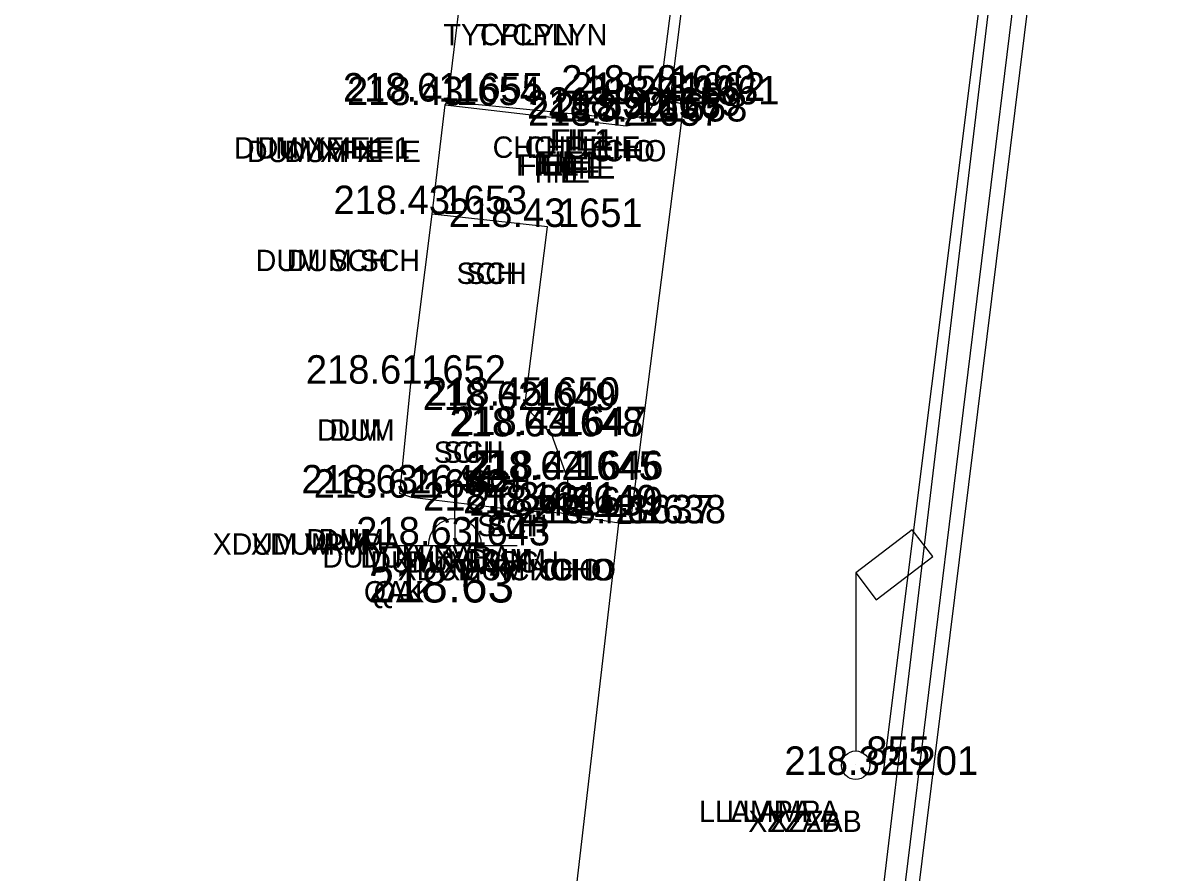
# Model space of a CAD drawing. Extents: x -471047 to -470889, y -1102859 to -1102000.
# Drawn here: x -470984.24 to -470967.99, y -1102446.24 to -1102434.32 of the extents above; entities that cross this region are included whole.
import ezdxf

# ---------------------------------------------------------------- set-up
doc = ezdxf.new("R2010")
doc.units = 0
for name, color, linetype in [('Vrstva 1', 7, 'Continuous'), ('Vrstva 10', 7, 'Continuous'), ('Vrstva 13', 7, 'Continuous'), ('Vrstva 17', 7, 'Continuous'), ('Vrstva 2', 7, 'Continuous'), ('Vrstva 22', 7, 'Continuous'), ('Vrstva 23', 7, 'Continuous'), ('Vrstva 28', 7, 'Continuous'), ('Vrstva 34', 7, 'Continuous'), ('Vrstva 35', 7, 'Continuous'), ('Vrstva 36', 7, 'Continuous'), ('Vrstva 38', 7, 'Continuous'), ('Vrstva 5', 7, 'Continuous'), ('Vrstva 7', 7, 'Continuous'), ('Vrstva 8', 7, 'Continuous')]:
    doc.layers.add(name, color=color, linetype=linetype)

msp = doc.modelspace()

# ---------------------------------------------------------------- linework, layer by layer
at = {"layer": 'Vrstva 1'}
for points in [[(-471040.344, -1102858.385), (-471031.676, -1102846.187), (-471026.357, -1102838.629), (-471023.212, -1102833.975), (-471019.21, -1102827.465), (-471016.861, -1102823.272), (-471013.099, -1102815.912), (-471010.824, -1102810.955), (-471007.329, -1102802.292), (-471005.34, -1102796.515), (-471002.842, -1102787.838), (-471001.3, -1102780.997), (-471000.19, -1102774.713), (-470999.247, -1102768.204), (-470998.794, -1102764.784), (-470997.199, -1102751.812), (-470994.899, -1102732.807), (-470992.551, -1102713.262), (-470990.326, -1102694.887), (-470988.122, -1102676.57), (-470985.812, -1102657.305), (-470983.537, -1102638.407), (-470981.386, -1102620.622), (-470979.843, -1102608.014), (-470976.377, -1102579.253), (-470972.945, -1102550.69), (-470970.475, -1102530.206), (-470967.905, -1102508.801), (-470965.053, -1102485.131), (-470962.734, -1102465.9), (-470960.173, -1102444.812), (-470957.795, -1102425.103), (-470954.965, -1102401.839), (-470953.834, -1102392.574), (-470952.33, -1102379.985), (-470950.744, -1102366.853), (-470948.978, -1102352.106), (-470947.037, -1102335.844), (-470944.949, -1102318.462), (-470944.013, -1102310.745), (-470942.39, -1102297.267), (-470939.519, -1102273.45), (-470937.593, -1102257.43), (-470936.064, -1102244.81), (-470934.114, -1102228.634), (-470931.621, -1102207.856), (-470929.536, -1102190.857), (-470926.572, -1102166.31), (-470924.91, -1102152.663), (-470923.413, -1102140.333), (-470921.923, -1102127.669), (-470921.155, -1102120.084), (-470920.446, -1102109.574), (-470919.912, -1102099.137), (-470919.63, -1102088.981), (-470919.523, -1102081.193), (-470919.563, -1102070.395), (-470919.714, -1102064.236), (-470920.134, -1102054.704), (-470920.462, -1102047.615), (-470920.599, -1102044.52), (-470920.743, -1102041.873), (-470921.125, -1102034.455), (-470921.774, -1102030.337), (-470922.418, -1102027.787), (-470923.734, -1102023.93), (-470924.872, -1102021.434), (-470926.752, -1102018.182), (-470927.953, -1102016.45), (-470929.616, -1102014.424), (-470932.252, -1102011.756), (-470935.111, -1102009.425), (-470938.391, -1102007.371), (-470942.651, -1102005.401)], [(-471041.328, -1102857.18), (-471032.144, -1102844.242), (-471027.583, -1102837.763), (-471024.388, -1102833.028), (-471020.451, -1102826.6), (-471018.089, -1102822.378), (-471014.542, -1102815.445), (-471012.233, -1102810.418), (-471009.247, -1102803.108), (-471006.795, -1102796.098), (-471004.315, -1102787.532), (-471002.782, -1102780.723), (-471001.674, -1102774.458), (-471000.75, -1102768.095), (-471000.28, -1102764.601), (-470998.692, -1102751.741), (-470996.378, -1102732.635), (-470994.028, -1102713.058), (-470991.808, -1102694.749), (-470989.616, -1102676.447), (-470987.284, -1102657.013), (-470985.031, -1102638.272), (-470982.87, -1102620.431), (-470981.334, -1102607.933), (-470977.881, -1102579.263), (-470974.429, -1102550.492), (-470971.964, -1102530.054), (-470969.391, -1102508.607), (-470966.54, -1102484.984), (-470964.231, -1102465.853), (-470961.679, -1102444.752), (-470959.304, -1102425.078), (-470956.455, -1102401.634), (-470955.339, -1102392.489), (-470953.812, -1102379.71), (-470952.249, -1102366.808), (-470950.479, -1102352.023), (-470948.536, -1102335.868), (-470946.426, -1102318.233), (-470945.493, -1102310.531), (-470943.864, -1102297.013), (-470940.984, -1102273.071), (-470939.078, -1102257.195), (-470937.559, -1102244.684), (-470935.592, -1102228.353), (-470933.101, -1102207.653), (-470931.011, -1102190.57), (-470928.046, -1102166.021), (-470926.409, -1102152.578), (-470924.898, -1102140.121), (-470923.427, -1102127.544), (-470922.647, -1102119.826), (-470921.919, -1102109.229), (-470921.42, -1102099.134), (-470921.127, -1102089.016), (-470921.023, -1102081.453), (-470921.061, -1102070.468), (-470921.209, -1102064.314), (-470921.666, -1102053.966), (-470922.156, -1102043.345), (-470922.299, -1102039.934), (-470922.637, -1102034.36), (-470923.091, -1102031.241), (-470923.847, -1102028.247), (-470925.083, -1102024.594), (-470926.222, -1102022.086), (-470928.04, -1102018.943), (-470929.138, -1102017.357), (-470930.929, -1102015.175), (-470933.062, -1102013.049), (-470936.379, -1102010.368), (-470939.169, -1102008.662), (-470942.899, -1102006.906), (-470945.661, -1102005.908)], [(-471043.557, -1102855.955), (-471035.129, -1102844.026), (-471029.872, -1102836.499), (-471026.577, -1102831.578), (-471022.675, -1102825.415), (-471020.123, -1102821.053), (-471016.667, -1102814.59), (-471014.208, -1102809.45), (-471011.177, -1102802.451), (-471008.55, -1102795.333), (-471006.082, -1102787.209), (-471004.464, -1102780.376), (-471003.265, -1102774.167), (-471002.327, -1102767.948), (-471001.636, -1102762.527), (-471000.297, -1102751.605), (-470997.959, -1102732.524), (-470995.602, -1102712.802), (-470993.412, -1102694.623), (-470991.21, -1102676.17), (-470988.891, -1102656.857), (-470986.625, -1102638.083), (-470984.455, -1102620.195), (-470982.936, -1102607.733), (-470979.497, -1102579.223), (-470976.023, -1102550.279), (-470973.554, -1102529.822), (-470970.991, -1102508.497), (-470968.146, -1102484.787), (-470965.835, -1102465.72), (-470963.284, -1102444.529), (-470960.91, -1102424.942), (-470958.043, -1102401.343), (-470956.946, -1102392.356), (-470955.396, -1102379.408), (-470953.851, -1102366.636), (-470952.049, -1102351.733), (-470950.124, -1102335.611), (-470948.034, -1102318.083), (-470947.094, -1102310.328), (-470945.421, -1102296.51), (-470942.58, -1102272.848), (-470940.675, -1102256.948), (-470939.176, -1102244.526), (-470937.187, -1102228.174), (-470934.708, -1102207.467), (-470932.621, -1102190.433), (-470929.634, -1102165.778), (-470928.004, -1102152.415), (-470926.45, -1102139.595), (-470925.003, -1102127.418), (-470924.249, -1102119.695), (-470923.515, -1102109.093), (-470923.018, -1102099.069), (-470922.711, -1102088.911), (-470922.643, -1102081.356), (-470922.797, -1102070.414), (-470923.018, -1102064.454), (-470923.52, -1102053.203), (-470923.823, -1102047.529), (-470924.123, -1102041.506), (-470924.462, -1102037.486), (-470924.934, -1102031.904), (-470925.664, -1102028.672), (-470926.771, -1102025.506), (-470927.959, -1102022.914), (-470929.674, -1102020.028), (-470930.76, -1102018.498), (-470932.447, -1102016.478), (-470935.215, -1102013.816), (-470937.644, -1102011.98), (-470940.381, -1102010.371), (-470943.968, -1102008.669), (-470947.145, -1102007.524), (-470950.874, -1102006.74)], [(-471044.756, -1102855.056), (-471036.376, -1102843.177), (-471031.167, -1102835.741), (-471027.859, -1102830.8), (-471023.934, -1102824.593), (-471021.43, -1102820.312), (-471018.011, -1102813.91), (-471015.536, -1102808.75), (-471012.578, -1102801.897), (-471009.95, -1102794.77), (-471007.561, -1102786.914), (-471005.936, -1102780.074), (-471004.727, -1102773.818), (-471003.828, -1102767.827), (-471003.121, -1102762.345), (-471001.787, -1102751.467), (-470999.446, -1102732.348), (-470997.073, -1102712.539), (-470994.902, -1102694.521), (-470992.696, -1102676.023), (-470990.376, -1102656.68), (-470988.131, -1102638.071), (-470985.947, -1102620.018), (-470984.417, -1102607.512), (-470980.993, -1102579.08), (-470977.514, -1102550.137), (-470975.048, -1102529.649), (-470972.488, -1102508.37), (-470969.618, -1102484.508), (-470967.34, -1102465.669), (-470964.767, -1102444.39), (-470962.402, -1102424.781), (-470959.534, -1102401.193), (-470958.432, -1102392.151), (-470956.883, -1102379.208), (-470955.335, -1102366.424), (-470953.535, -1102351.506), (-470951.606, -1102335.399), (-470949.519, -1102317.94), (-470948.575, -1102310.159), (-470946.889, -1102296.144), (-470944.056, -1102272.618), (-470942.139, -1102256.659), (-470940.657, -1102244.341), (-470938.638, -1102227.749), (-470936.19, -1102207.298), (-470934.102, -1102190.255), (-470931.124, -1102165.639), (-470929.492, -1102152.254), (-470927.915, -1102139.252), (-470926.46, -1102127.103), (-470925.74, -1102119.604), (-470925.012, -1102108.913), (-470924.523, -1102099.054), (-470924.217, -1102088.866), (-470924.148, -1102081.334), (-470924.301, -1102070.391), (-470924.518, -1102064.43), (-470924.97, -1102054.435), (-470925.588, -1102041.569), (-470925.963, -1102035.313), (-470926.405, -1102032.225), (-470927.078, -1102029.198), (-470928.123, -1102026.148), (-470929.318, -1102023.558), (-470930.84, -1102020.97), (-470931.868, -1102019.515), (-470933.443, -1102017.605), (-470936.26, -1102014.885), (-470938.429, -1102013.255), (-470941.213, -1102011.639), (-470944.847, -1102009.927), (-470947.723, -1102008.912), (-470951.444, -1102008.161), (-470954.511, -1102007.931), (-470957.895, -1102008.041)]]:
    msp.add_spline(points, degree=3, dxfattribs=at)
at = {"layer": 'Vrstva 10'}
for p, q in [((-470978.279, -1102435.42), (-470977.309, -1102427.582)), ((-470978.499, -1102437), (-470978.313, -1102435.465)), ((-470978.313, -1102435.465), (-470978.279, -1102435.42)), ((-470978.799, -1102439.383), (-470978.499, -1102437)), ((-470978.951, -1102440.922), (-470978.799, -1102439.383)), ((-470978.783, -1102440.976), (-470978.951, -1102440.922)), ((-470976.681, -1102441.195), (-470977.236, -1102441.162)), ((-470976.585, -1102441.227), (-470976.681, -1102441.195)), ((-470975.875, -1102441.337), (-470976.585, -1102441.227)), ((-470976.537, -1102447.015), (-470975.875, -1102441.337))]:
    msp.add_line(p, q, dxfattribs=at)
at = {"layer": 'Vrstva 13'}
for p, q in [((-470978.178, -1102441.275), (-470978.178, -1102440.775)), ((-470978.178, -1102441.275), (-470978.178, -1102441.65)), ((-470978.178, -1102441.3), (-470978.178, -1102441.3)), ((-470979.053, -1102441.65), (-470977.303, -1102441.65)), ((-470978.178, -1102441.65), (-470977.803, -1102441.65))]:
    msp.add_line(p, q, dxfattribs=at)
for start, end in [(90, 180), (0, 90)]:
    msp.add_arc((-470978.178, -1102441.65), 0.375, start, end, dxfattribs=at)
at = {"layer": 'Vrstva 17'}
for p, q in [((-470976.88, -1102437.18), (-470978.499, -1102437)), ((-470977.197, -1102439.69), (-470976.88, -1102437.18)), ((-470976.819, -1102440.099), (-470977.197, -1102439.69)), ((-470976.591, -1102440.718), (-470976.819, -1102440.099)), ((-470976.585, -1102441.227), (-470976.591, -1102440.718))]:
    msp.add_line(p, q, dxfattribs=at)
at = {"layer": 'Vrstva 2'}
msp.add_line((-470972.167, -1102444.871), (-470970.199, -1102429.162), dxfattribs=at)
at = {"layer": 'Vrstva 23'}
for p, q in [((-470971.756, -1102441.429), (-470972.551, -1102442.034)), ((-470971.466, -1102441.806), (-470971.756, -1102441.429)), ((-470972.264, -1102442.412), (-470971.466, -1102441.806)), ((-470972.551, -1102442.034), (-470972.551, -1102444.534)), ((-470972.551, -1102442.034), (-470972.264, -1102442.412))]:
    msp.add_line(p, q, dxfattribs=at)
msp.add_circle((-470972.551, -1102444.734), 0.2, dxfattribs=at)
at = {"layer": 'Vrstva 28'}
msp.add_line((-470977.236, -1102441.162), (-470978.783, -1102440.976), dxfattribs=at)
at = {"layer": 'Vrstva 34'}
for p, q in [((-470975.3, -1102435.31), (-470975.3, -1102435.31)), ((-470978.31, -1102435.47), (-470978.31, -1102435.47)), ((-470978.28, -1102435.42), (-470978.28, -1102435.42)), ((-470975.16, -1102435.41), (-470975.16, -1102435.41)), ((-470974.96, -1102435.46), (-470974.96, -1102435.46)), ((-470975.78, -1102435.66), (-470975.78, -1102435.66)), ((-470975.49, -1102435.62), (-470975.49, -1102435.62)), ((-470975.41, -1102435.7), (-470975.41, -1102435.7)), ((-470975.77, -1102435.76), (-470975.77, -1102435.76)), ((-470978.5, -1102437), (-470978.5, -1102437)), ((-470976.88, -1102437.18), (-470976.88, -1102437.18)), ((-470978.8, -1102439.38), (-470978.8, -1102439.38)), ((-470977.25, -1102439.75), (-470977.25, -1102439.75)), ((-470977.2, -1102439.69), (-470977.2, -1102439.69)), ((-470976.87, -1102440.12), (-470976.87, -1102440.12)), ((-470976.82, -1102440.1), (-470976.82, -1102440.1)), ((-470976.64, -1102440.73), (-470976.64, -1102440.73)), ((-470976.59, -1102440.72), (-470976.59, -1102440.72)), ((-470978.95, -1102440.92), (-470978.95, -1102440.92)), ((-470978.78, -1102440.98), (-470978.78, -1102440.98)), ((-470977.24, -1102441.16), (-470977.24, -1102441.16)), ((-470976.68, -1102441.2), (-470976.68, -1102441.2)), ((-470976.59, -1102441.23), (-470976.59, -1102441.23)), ((-470975.88, -1102441.34), (-470975.88, -1102441.34)), ((-470975.71, -1102441.34), (-470975.71, -1102441.34)), ((-470978.18, -1102441.65), (-470978.18, -1102441.65)), ((-470972.55, -1102444.73), (-470972.55, -1102444.73)), ((-470972.17, -1102444.87), (-470972.17, -1102444.87))]:
    msp.add_line(p, q, dxfattribs=at)
at = {"layer": 'Vrstva 5'}
msp.add_line((-470971.765, -1102447.282), (-470969.566, -1102429.53), dxfattribs=at)
at = {"layer": 'Vrstva 7'}
for p, q in [((-470975.296, -1102435.308), (-470973.936, -1102424.663)), ((-470972.256, -1102447.249), (-470970.115, -1102429.388)), ((-470975.492, -1102435.619), (-470975.296, -1102435.308)), ((-470978.279, -1102435.42), (-470975.776, -1102435.663)), ((-470975.776, -1102435.663), (-470975.492, -1102435.619))]:
    msp.add_line(p, q, dxfattribs=at)
at = {"layer": 'Vrstva 8'}
for p, q in [((-470975.157, -1102435.41), (-470973.801, -1102424.565)), ((-470971.97, -1102447.332), (-470969.77, -1102429.442)), ((-470978.313, -1102435.465), (-470975.772, -1102435.759)), ((-470975.714, -1102441.339), (-470974.964, -1102435.462)), ((-470975.407, -1102435.698), (-470975.157, -1102435.41)), ((-470974.964, -1102435.462), (-470975.157, -1102435.41)), ((-470975.772, -1102435.759), (-470975.407, -1102435.698)), ((-470975.875, -1102441.337), (-470975.714, -1102441.339))]:
    msp.add_line(p, q, dxfattribs=at)

# ---------------------------------------------------------------- texts
at = {"layer": 'Vrstva 22'}
msp.add_text('218.63', height=0.5, dxfattribs=at).set_placement((-470979.393, -1102442.45))
at = {"layer": 'Vrstva 35'}
for s, p in [('TYCPLYN', (-470978.339, -1102434.63)), ('TYCPLYN', (-470977.889, -1102434.63)), ('FIE1', (-470976.842, -1102436.11)), ('FIE1', (-470976.8, -1102436.11)), ('DUM XFIE1', (-470981.28, -1102436.22)), ('DUM XFIE', (-470981.098, -1102436.27)), ('DUM XFIE1', (-470980.947, -1102436.22)), ('DUM XFIE', (-470980.574, -1102436.27)), ('CHO FIE', (-470977.648, -1102436.21)), ('CHO FIE', (-470977.199, -1102436.21)), ('CHO', (-470976.261, -1102436.26)), ('CHO', (-470976.099, -1102436.26)), ('FIE1', (-470977.322, -1102436.46)), ('FIE1', (-470977.28, -1102436.46)), ('FIE1', (-470977.032, -1102436.42)), ('FIE1', (-470976.99, -1102436.42)), ('FIE', (-470977.057, -1102436.56)), ('FIE', (-470976.909, -1102436.56)), ('FIE', (-470976.698, -1102436.5)), ('FIE', (-470976.549, -1102436.5)), ('DUM SCH', (-470980.975, -1102437.8)), ('DUM SCH', (-470980.539, -1102437.8)), ('SCH', (-470978.155, -1102437.98)), ('SCH', (-470978.019, -1102437.98)), ('DUM', (-470980.115, -1102440.18)), ('DUM', (-470979.939, -1102440.18)), ('SCH', (-470978.475, -1102440.49)), ('SCH', (-470978.339, -1102440.49)), ('SCH', (-470978.095, -1102440.9)), ('SCH', (-470977.959, -1102440.9)), ('SCH', (-470977.865, -1102441.52)), ('SCH', (-470977.729, -1102441.52)), ('XDUM VRA', (-470981.58, -1102441.78)), ('XDUM VRA', (-470981.044, -1102441.78)), ('DUM', (-470980.265, -1102441.72)), ('DUM', (-470980.089, -1102441.72)), ('DUM XVRA', (-470980.04, -1102441.96)), ('DUM XVRA', (-470979.504, -1102441.96)), ('DUM', (-470977.995, -1102442)), ('DUM', (-470977.819, -1102442)), ('DUM XSCH', (-470979.365, -1102442.03)), ('XDUM XCHO', (-470978.981, -1102442.14)), ('DUM XSCH', (-470978.854, -1102442.03)), ('XDUM XCHO', (-470978.369, -1102442.14)), ('CHO', (-470977.011, -1102442.14)), ('CHO', (-470976.849, -1102442.14)), ('QAK', (-470979.455, -1102442.45)), ('QAK', (-470979.319, -1102442.45)), ('LLAMPA', (-470974.75, -1102445.53)), ('LLAMPA', (-470974.364, -1102445.53)), ('XZZAB', (-470974.059, -1102445.67)), ('XZZAB', (-470973.759, -1102445.67))]:
    msp.add_text(s, height=0.3, dxfattribs=at).set_placement(p)
at = {"layer": 'Vrstva 36'}
for s, p in [(' 1655', (-470978.28, -1102435.42)), (' 1660', (-470975.3, -1102435.31)), (' 1662', (-470975.16, -1102435.41)), (' 1661', (-470974.96, -1102435.46)), (' 1654', (-470978.31, -1102435.47)), (' 1659', (-470975.49, -1102435.62)), (' 1656', (-470975.78, -1102435.66)), (' 1657', (-470975.77, -1102435.76)), (' 1658', (-470975.41, -1102435.7)), (' 1653', (-470978.5, -1102437)), (' 1651', (-470976.88, -1102437.18)), (' 1652', (-470978.8, -1102439.38)), (' 1649', (-470977.25, -1102439.75)), (' 1650', (-470977.2, -1102439.69)), (' 1648', (-470976.87, -1102440.12)), (' 1647', (-470976.82, -1102440.1)), (' 1645', (-470976.64, -1102440.73)), (' 1646', (-470976.59, -1102440.72)), (' 1644', (-470978.95, -1102440.92)), (' 1642', (-470978.78, -1102440.98)), (' 1641', (-470977.24, -1102441.16)), (' 1640', (-470976.68, -1102441.2)), (' 1639', (-470976.59, -1102441.23)), (' 1637', (-470975.88, -1102441.34)), (' 1638', (-470975.71, -1102441.34)), (' 1643', (-470978.18, -1102441.65)), (' 855', (-470972.55, -1102444.73)), (' 1201', (-470972.17, -1102444.87))]:
    msp.add_text(s, height=0.4, dxfattribs=at).set_placement(p)
at = {"layer": 'Vrstva 38'}
for s, p in [('218.61 ', (-470979.75, -1102435.42)), ('218.58 ', (-470976.684, -1102435.31)), ('218.43 ', (-470976.543, -1102435.41)), ('218.42 ', (-470976.341, -1102435.46)), ('218.43 ', (-470979.693, -1102435.47)), ('218.59 ', (-470976.874, -1102435.62)), ('218.59 ', (-470977.164, -1102435.66)), ('218.42 ', (-470977.151, -1102435.76)), ('218.42 ', (-470976.791, -1102435.7)), ('218.43 ', (-470979.883, -1102437)), ('218.43 ', (-470978.263, -1102437.18)), ('218.61 ', (-470980.27, -1102439.38)), ('218.62 ', (-470978.631, -1102439.75)), ('218.45 ', (-470978.584, -1102439.69)), ('218.63 ', (-470978.253, -1102440.12)), ('218.44 ', (-470978.202, -1102440.1)), ('218.62 ', (-470978.021, -1102440.73)), ('218.44 ', (-470977.972, -1102440.72)), ('218.63 ', (-470980.333, -1102440.92)), ('218.62 ', (-470980.161, -1102440.98)), ('218.63 ', (-470978.623, -1102441.16)), ('218.63 ', (-470978.063, -1102441.2)), ('218.45 ', (-470977.974, -1102441.23)), ('218.42 ', (-470977.261, -1102441.34)), ('218.43 ', (-470977.093, -1102441.34)), ('218.63 ', (-470979.563, -1102441.65)), ('218.32 ', (-470973.551, -1102444.87))]:
    msp.add_text(s, height=0.4, dxfattribs=at).set_placement(p)

doc.saveas('drawing.dxf')
